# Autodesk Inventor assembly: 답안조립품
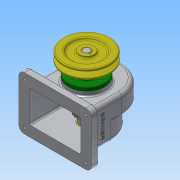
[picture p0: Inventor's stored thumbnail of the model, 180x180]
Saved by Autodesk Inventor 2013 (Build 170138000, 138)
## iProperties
Created: 2017-11
Part Number: 답안조립품
Document SubType Name: Assembly
Designer: Administrator
Author: Administrator
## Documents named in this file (14)
- C:\Users\Administrator\Desktop\471108V1028\답안조립품.iam
- C:\Users\Administrator\Desktop\471108V1028\V-벨트풀리.ipt
- C:\Users\Administrator\Desktop\471108V1028\뒤커버.ipt
- C:\Users\Administrator\Desktop\471108V1028\멈춤나사 - M4 x 10.ipt
- 멈춤나사 - M4 x 10.ipt
- C:\Users\Administrator\Desktop\471108V1028\베어링 6002.ipt
- C:\Users\Administrator\Desktop\471108V1028\본체.ipt
- C:\Users\Administrator\Desktop\471108V1028\볼트 M3 x 8.ipt
- C:\Users\Administrator\Desktop\471108V1028\스퍼기어.ipt
- C:\Users\Administrator\Desktop\471108V1028\앞커버.ipt
- C:\Users\Administrator\Desktop\471108V1028\오일 실 15 30 7.ipt
- C:\Users\Administrator\Desktop\471108V1028\축.ipt
- C:\Users\Administrator\Desktop\471108V1028\키 - 5 x 5 x 18.ipt
- C:\Users\Administrator\Desktop\471108V1028\키 - 6 x 6 x 22.ipt
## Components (1 placed, 1 different names)
1. V-벨트풀리:1 — 플러쉬:1
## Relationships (1: Flush 1)
- 플러쉬:1 [Flush]: V-벨트풀리:1
